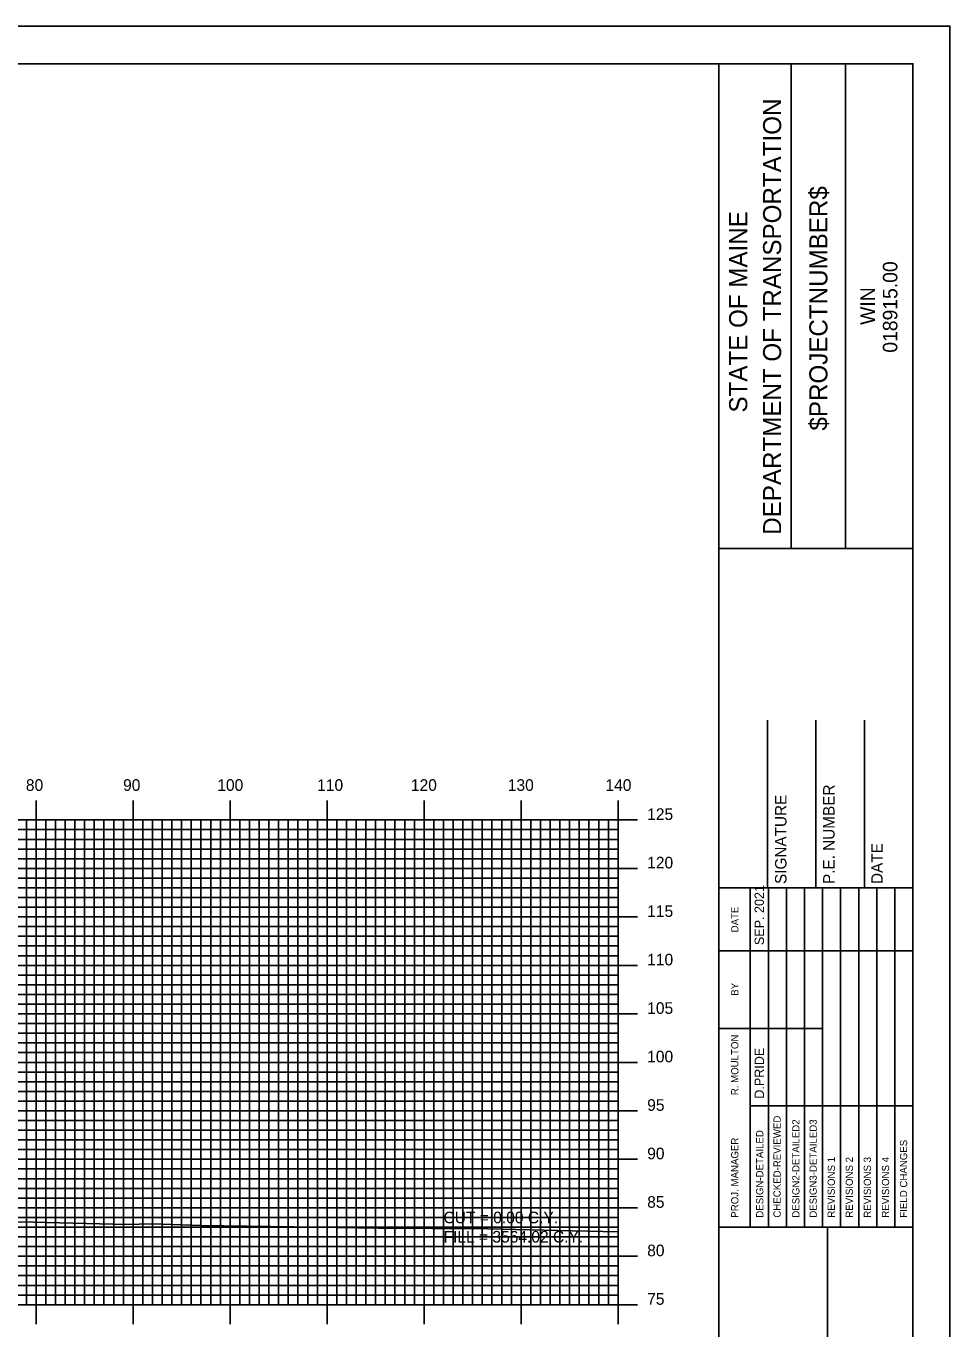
# Model space of a CAD drawing. Extents: x 856084 to 856427, y 364366 to 364586.
# Drawn here: x 856328.8 to 856424, y 364451.3 to 364585.7 of the extents above; entities that cross this region are included whole.
import ezdxf

# ---------------------------------------------------------------- set-up
doc = ezdxf.new("R2010")
doc.units = 0
for name, color, linetype in [('BORDER', 7, 'Continuous'), ('D_Text_Standard', 7, 'Continuous'), ('H_V ANNOTATION', 7, 'Continuous'), ('MAJOR', 7, 'Continuous'), ('MINOR', 7, 'Continuous'), ('PLOT BOUNDARY', 7, 'Continuous'), ('S_Roadway_Centerline', 7, 'Continuous')]:
    doc.layers.add(name, color=color, linetype=linetype)

msp = doc.modelspace()

# ---------------------------------------------------------------- linework, layer by layer
at = {"layer": 'BORDER'}
for p, q in [((856400.2, 364371.79), (856400.2, 364581.79)), ((856407.65, 364531.78), (856407.65, 364581.78)), ((856413.24, 364531.78), (856413.24, 364581.78)), ((856400.2, 364531.78), (856420.2, 364531.78)), ((856405.2, 364496.79), (856405.2, 364514.09)), ((856410.2, 364496.79), (856410.2, 364514.09)), ((856415.2, 364496.79), (856415.2, 364514.09)), ((856400.2, 364496.79), (856420.2, 364496.79)), ((856400.2, 364461.79), (856420.2, 364461.79)), ((856411.38, 364391.79), (856411.38, 364461.79))]:
    msp.add_line(p, q, dxfattribs=at)
msp.add_lwpolyline([(856100.2, 364371.79), (856420.2, 364371.79), (856420.2, 364581.79), (856100.2, 364581.79)], close=True, dxfattribs=at)
for points in [[(856403.43, 364490.29), (856403.43, 364496.79)], [(856405.29, 364461.8), (856405.29, 364496.79)], [(856407.15, 364496.79), (856407.15, 364461.8)], [(856409.02, 364461.8), (856409.02, 364496.79)], [(856410.88, 364461.8), (856410.88, 364496.79)], [(856412.74, 364461.8), (856412.74, 364496.79)], [(856414.61, 364461.8), (856414.61, 364496.79)], [(856416.47, 364461.8), (856416.47, 364496.79)], [(856418.33, 364461.8), (856418.33, 364496.79)], [(856403.43, 364461.8), (856403.43, 364495.38)], [(856400.2, 364490.29), (856420.2, 364490.29)], [(856400.2, 364482.29), (856403.43, 364482.29)], [(856403.43, 364482.29), (856410.88, 364482.29)], [(856403.43, 364474.29), (856420.2, 364474.29)]]:
    msp.add_lwpolyline(points, dxfattribs=at)
at = {"layer": 'MAJOR'}
for p, q in [((856329.8, 364505.79), (856329.8, 364503.79)), ((856339.8, 364505.79), (856339.8, 364503.79)), ((856349.8, 364505.79), (856349.8, 364503.79)), ((856359.8, 364505.79), (856359.8, 364503.79)), ((856369.8, 364505.79), (856369.8, 364503.79)), ((856379.8, 364505.79), (856379.8, 364503.79)), ((856389.8, 364505.79), (856389.8, 364503.79)), ((856109.8, 364503.79), (856389.8, 364503.79)), ((856109.8, 364503.79), (856389.8, 364503.79)), ((856329.8, 364453.79), (856329.8, 364503.79)), ((856339.8, 364453.79), (856339.8, 364503.79)), ((856349.8, 364453.79), (856349.8, 364503.79)), ((856359.8, 364453.79), (856359.8, 364503.79)), ((856369.8, 364453.79), (856369.8, 364503.79)), ((856379.8, 364453.79), (856379.8, 364503.79)), ((856391.8, 364503.79), (856387.79, 364503.79)), ((856389.8, 364453.79), (856389.8, 364503.79)), ((856389.8, 364453.79), (856389.8, 364503.79)), ((856109.8, 364498.79), (856389.8, 364498.79)), ((856391.8, 364498.79), (856387.79, 364498.79)), ((856109.8, 364493.79), (856389.8, 364493.79)), ((856391.8, 364493.79), (856387.79, 364493.79)), ((856109.8, 364488.79), (856389.8, 364488.79)), ((856391.8, 364488.79), (856387.79, 364488.79)), ((856109.8, 364483.79), (856389.8, 364483.79)), ((856391.8, 364483.79), (856387.79, 364483.79)), ((856109.8, 364478.79), (856389.8, 364478.79)), ((856391.8, 364478.79), (856387.79, 364478.79)), ((856109.8, 364473.79), (856389.8, 364473.79)), ((856391.8, 364473.79), (856387.79, 364473.79)), ((856109.8, 364468.79), (856389.8, 364468.79)), ((856391.8, 364468.79), (856387.79, 364468.79)), ((856109.8, 364463.79), (856389.8, 364463.79)), ((856391.8, 364463.79), (856387.79, 364463.79)), ((856109.8, 364458.79), (856389.8, 364458.79)), ((856391.8, 364458.79), (856387.79, 364458.79)), ((856109.8, 364453.79), (856389.8, 364453.79)), ((856109.8, 364453.79), (856389.8, 364453.79)), ((856329.8, 364451.78), (856329.8, 364453.79)), ((856339.8, 364451.78), (856339.8, 364453.79)), ((856349.8, 364451.78), (856349.8, 364453.79)), ((856359.8, 364451.78), (856359.8, 364453.79)), ((856369.8, 364451.78), (856369.8, 364453.79)), ((856379.8, 364451.78), (856379.8, 364453.79)), ((856391.8, 364453.79), (856387.79, 364453.79)), ((856389.8, 364451.78), (856389.8, 364453.79))]:
    msp.add_line(p, q, dxfattribs=at)
at = {"layer": 'MINOR'}
for p, q in [((856328.8, 364453.79), (856328.8, 364503.79)), ((856330.8, 364453.79), (856330.8, 364503.79)), ((856331.8, 364453.79), (856331.8, 364503.79)), ((856332.8, 364453.79), (856332.8, 364503.79)), ((856333.8, 364453.79), (856333.8, 364503.79)), ((856334.8, 364453.79), (856334.8, 364503.79)), ((856335.8, 364453.79), (856335.8, 364503.79)), ((856336.8, 364453.79), (856336.8, 364503.79)), ((856337.8, 364453.79), (856337.8, 364503.79)), ((856338.8, 364453.79), (856338.8, 364503.79)), ((856340.8, 364453.79), (856340.8, 364503.79)), ((856341.8, 364453.79), (856341.8, 364503.79)), ((856342.8, 364453.79), (856342.8, 364503.79)), ((856343.8, 364453.79), (856343.8, 364503.79)), ((856344.8, 364453.79), (856344.8, 364503.79)), ((856345.8, 364453.79), (856345.8, 364503.79)), ((856346.8, 364453.79), (856346.8, 364503.79)), ((856347.8, 364453.79), (856347.8, 364503.79)), ((856348.8, 364453.79), (856348.8, 364503.79)), ((856350.8, 364453.79), (856350.8, 364503.79)), ((856351.8, 364453.79), (856351.8, 364503.79)), ((856352.8, 364453.79), (856352.8, 364503.79)), ((856353.8, 364453.79), (856353.8, 364503.79)), ((856354.8, 364453.79), (856354.8, 364503.79)), ((856355.8, 364453.79), (856355.8, 364503.79)), ((856356.8, 364453.79), (856356.8, 364503.79)), ((856357.8, 364453.79), (856357.8, 364503.79)), ((856358.8, 364453.79), (856358.8, 364503.79)), ((856360.8, 364453.79), (856360.8, 364503.79)), ((856361.8, 364453.79), (856361.8, 364503.79)), ((856362.8, 364453.79), (856362.8, 364503.79)), ((856363.8, 364453.79), (856363.8, 364503.79)), ((856364.8, 364453.79), (856364.8, 364503.79)), ((856365.8, 364453.79), (856365.8, 364503.79)), ((856366.8, 364453.79), (856366.8, 364503.79)), ((856367.8, 364453.79), (856367.8, 364503.79)), ((856368.8, 364453.79), (856368.8, 364503.79)), ((856370.8, 364453.79), (856370.8, 364503.79)), ((856371.8, 364453.79), (856371.8, 364503.79)), ((856372.8, 364453.79), (856372.8, 364503.79)), ((856373.8, 364453.79), (856373.8, 364503.79)), ((856374.8, 364453.79), (856374.8, 364503.79)), ((856375.8, 364453.79), (856375.8, 364503.79)), ((856376.8, 364453.79), (856376.8, 364503.79)), ((856377.8, 364453.79), (856377.8, 364503.79)), ((856378.8, 364453.79), (856378.8, 364503.79)), ((856380.8, 364453.79), (856380.8, 364503.79)), ((856381.8, 364453.79), (856381.8, 364503.79)), ((856382.8, 364453.79), (856382.8, 364503.79)), ((856383.8, 364453.79), (856383.8, 364503.79)), ((856384.8, 364453.79), (856384.8, 364503.79)), ((856385.8, 364453.79), (856385.8, 364503.79)), ((856386.8, 364453.79), (856386.8, 364503.79)), ((856387.8, 364453.79), (856387.8, 364503.79)), ((856388.8, 364453.79), (856388.8, 364503.79)), ((856109.8, 364502.79), (856389.8, 364502.79)), ((856389.8, 364502.79), (856387.79, 364502.79)), ((856109.8, 364501.79), (856389.8, 364501.79)), ((856389.8, 364501.79), (856387.79, 364501.79)), ((856109.8, 364500.79), (856389.8, 364500.79)), ((856109.8, 364499.79), (856389.8, 364499.79)), ((856389.8, 364500.79), (856387.79, 364500.79)), ((856389.8, 364499.79), (856387.79, 364499.79)), ((856109.8, 364497.79), (856389.8, 364497.79)), ((856389.8, 364497.79), (856387.79, 364497.79)), ((856109.8, 364496.79), (856389.8, 364496.79)), ((856109.8, 364495.79), (856389.8, 364495.79)), ((856389.8, 364496.79), (856387.79, 364496.79)), ((856389.8, 364495.79), (856387.79, 364495.79)), ((856109.8, 364494.79), (856389.8, 364494.79)), ((856389.8, 364494.79), (856387.79, 364494.79)), ((856109.8, 364492.79), (856389.8, 364492.79)), ((856109.8, 364491.79), (856389.8, 364491.79)), ((856389.8, 364492.79), (856387.79, 364492.79)), ((856389.8, 364491.79), (856387.79, 364491.79)), ((856109.8, 364490.79), (856389.8, 364490.79)), ((856389.8, 364490.79), (856387.79, 364490.79)), ((856109.8, 364489.79), (856389.8, 364489.79)), ((856389.8, 364489.79), (856387.79, 364489.79)), ((856109.8, 364487.79), (856389.8, 364487.79)), ((856389.8, 364487.79), (856387.79, 364487.79)), ((856109.8, 364486.79), (856389.8, 364486.79)), ((856389.8, 364486.79), (856387.79, 364486.79)), ((856109.8, 364485.79), (856389.8, 364485.79)), ((856389.8, 364485.79), (856387.79, 364485.79)), ((856109.8, 364484.79), (856389.8, 364484.79)), ((856389.8, 364484.79), (856387.79, 364484.79)), ((856109.8, 364482.79), (856389.8, 364482.79)), ((856389.8, 364482.79), (856387.79, 364482.79)), ((856109.8, 364481.79), (856389.8, 364481.79)), ((856389.8, 364481.79), (856387.79, 364481.79)), ((856109.8, 364480.79), (856389.8, 364480.79)), ((856109.8, 364479.79), (856389.8, 364479.79)), ((856389.8, 364480.79), (856387.79, 364480.79)), ((856389.8, 364479.79), (856387.79, 364479.79)), ((856109.8, 364477.79), (856389.8, 364477.79)), ((856389.8, 364477.79), (856387.79, 364477.79)), ((856109.8, 364476.79), (856389.8, 364476.79)), ((856109.8, 364475.79), (856389.8, 364475.79)), ((856389.8, 364476.79), (856387.79, 364476.79)), ((856389.8, 364475.79), (856387.79, 364475.79)), ((856109.8, 364474.79), (856389.8, 364474.79)), ((856389.8, 364474.79), (856387.79, 364474.79)), ((856109.8, 364472.79), (856389.8, 364472.79)), ((856389.8, 364472.79), (856387.79, 364472.79)), ((856109.8, 364471.79), (856389.8, 364471.79)), ((856389.8, 364471.79), (856387.79, 364471.79)), ((856109.8, 364470.79), (856389.8, 364470.79)), ((856389.8, 364470.79), (856387.79, 364470.79)), ((856109.8, 364469.79), (856389.8, 364469.79)), ((856389.8, 364469.79), (856387.79, 364469.79)), ((856109.8, 364467.79), (856389.8, 364467.79)), ((856389.8, 364467.79), (856387.79, 364467.79)), ((856109.8, 364466.79), (856389.8, 364466.79)), ((856389.8, 364466.79), (856387.79, 364466.79)), ((856109.8, 364465.79), (856389.8, 364465.79)), ((856109.8, 364464.79), (856389.8, 364464.79)), ((856389.8, 364465.79), (856387.79, 364465.79)), ((856389.8, 364464.79), (856387.79, 364464.79)), ((856109.8, 364462.79), (856389.8, 364462.79)), ((856389.8, 364462.79), (856387.79, 364462.79)), ((856109.8, 364461.79), (856389.8, 364461.79)), ((856109.8, 364460.79), (856389.8, 364460.79)), ((856389.8, 364461.79), (856387.79, 364461.79)), ((856389.8, 364460.79), (856387.79, 364460.79)), ((856109.8, 364459.79), (856389.8, 364459.79)), ((856389.8, 364459.79), (856387.79, 364459.79)), ((856109.8, 364457.79), (856389.8, 364457.79)), ((856109.8, 364456.79), (856389.8, 364456.79)), ((856389.8, 364457.79), (856387.79, 364457.79)), ((856389.8, 364456.79), (856387.79, 364456.79)), ((856109.8, 364455.79), (856389.8, 364455.79)), ((856389.8, 364455.79), (856387.79, 364455.79)), ((856109.8, 364454.79), (856389.8, 364454.79)), ((856389.8, 364454.79), (856387.79, 364454.79))]:
    msp.add_line(p, q, dxfattribs=at)
at = {"layer": 'PLOT BOUNDARY'}
msp.add_lwpolyline([(856084.01, 364365.67), (856424.01, 364365.67), (856424.01, 364585.67), (856084.01, 364585.67)], close=True, dxfattribs=at)
at = {"layer": 'S_Roadway_Centerline'}
msp.add_lwpolyline([(856324.92, 364462.38), (856329.55, 364462.29), (856339.08, 364462.07), (856341.78, 364462.14), (856346.7, 364461.96), (856358.86, 364461.78), (856365.08, 364461.7), (856376.34, 364461.61), (856385.09, 364461.42), (856389.8, 364461.32)], dxfattribs=at)

# ---------------------------------------------------------------- texts
at = {"layer": 'BORDER'}
for s, height, p in [('DEPARTMENT OF TRANSPORTATION', 1.8635, (856406.61, 364533.2)), ('$PROJECTNUMBER$', 1.8635, (856411.38, 364543.95)), ('STATE OF MAINE', 1.8635, (856403.11, 364545.81)), ('018915.00', 1.491, (856418.59, 364551.98)), ('WIN', 1.491, (856416.27, 364554.85)), ('P.E. NUMBER', 1.1811, (856412.12, 364497.18)), ('SIGNATURE', 1.181, (856407.16, 364497.18)), ('DATE', 1.181, (856417.08, 364497.18)), ('SEP. 2021', 0.969, (856404.84, 364490.88)), ('DATE', 0.743, (856402.2, 364492.2)), ('BY', 0.743, (856402.2, 364485.66)), ('R. MOULTON', 0.745, (856402.2, 364475.4)), ('D.PRIDE', 0.969, (856404.84, 364475.04)), ('CHECKED-REVIEWED', 0.7455, (856406.56, 364462.77)), ('DESIGN2-DETAILED2', 0.7455, (856408.5, 364462.77)), ('DESIGN3-DETAILED3', 0.7455, (856410.28, 364462.77)), ('DESIGN-DETAILED', 0.7455, (856404.77, 364462.77)), ('PROJ. MANAGER', 0.7455, (856402.2, 364462.77)), ('FIELD CHANGES', 0.7455, (856419.6, 364462.77)), ('REVISIONS 1', 0.7455, (856412.15, 364462.77)), ('REVISIONS 2', 0.7455, (856414.01, 364462.77)), ('REVISIONS 3', 0.7455, (856415.87, 364462.77)), ('REVISIONS 4', 0.7455, (856417.74, 364462.77))]:
    msp.add_text(s, height=height, rotation=90, dxfattribs=at).set_placement(p)
at = {"layer": 'D_Text_Standard'}
for s, p in [('CUT = 0.00 C.Y.', (856371.8, 364462.19)), ('FILL = 3564.02 C.Y.', (856371.8, 364460.2))]:
    msp.add_text(s, height=1.2, dxfattribs=at).set_placement(p)
at = {"layer": 'H_V ANNOTATION'}
for s, p in [('80', (856328.75, 364506.79)), ('90', (856338.77, 364506.79)), ('100', (856348.48, 364506.79)), ('110', (856358.78, 364506.79)), ('120', (856368.44, 364506.79)), ('130', (856378.43, 364506.79)), ('140', (856388.5, 364506.79)), ('125', (856392.8, 364503.79)), ('120', (856392.8, 364498.79)), ('115', (856392.8, 364493.79)), ('110', (856392.8, 364488.79)), ('105', (856392.8, 364483.79)), ('100', (856392.8, 364478.79)), ('95', (856392.8, 364473.79)), ('90', (856392.8, 364468.79)), ('85', (856392.8, 364463.79)), ('80', (856392.8, 364458.79)), ('75', (856392.8, 364453.79))]:
    msp.add_text(s, height=1.2, dxfattribs=at).set_placement(p)

doc.saveas('drawing.dxf')
